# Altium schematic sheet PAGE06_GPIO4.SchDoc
size 381 x 381 mm; SheetNumber: 7; SheetTotal: 28
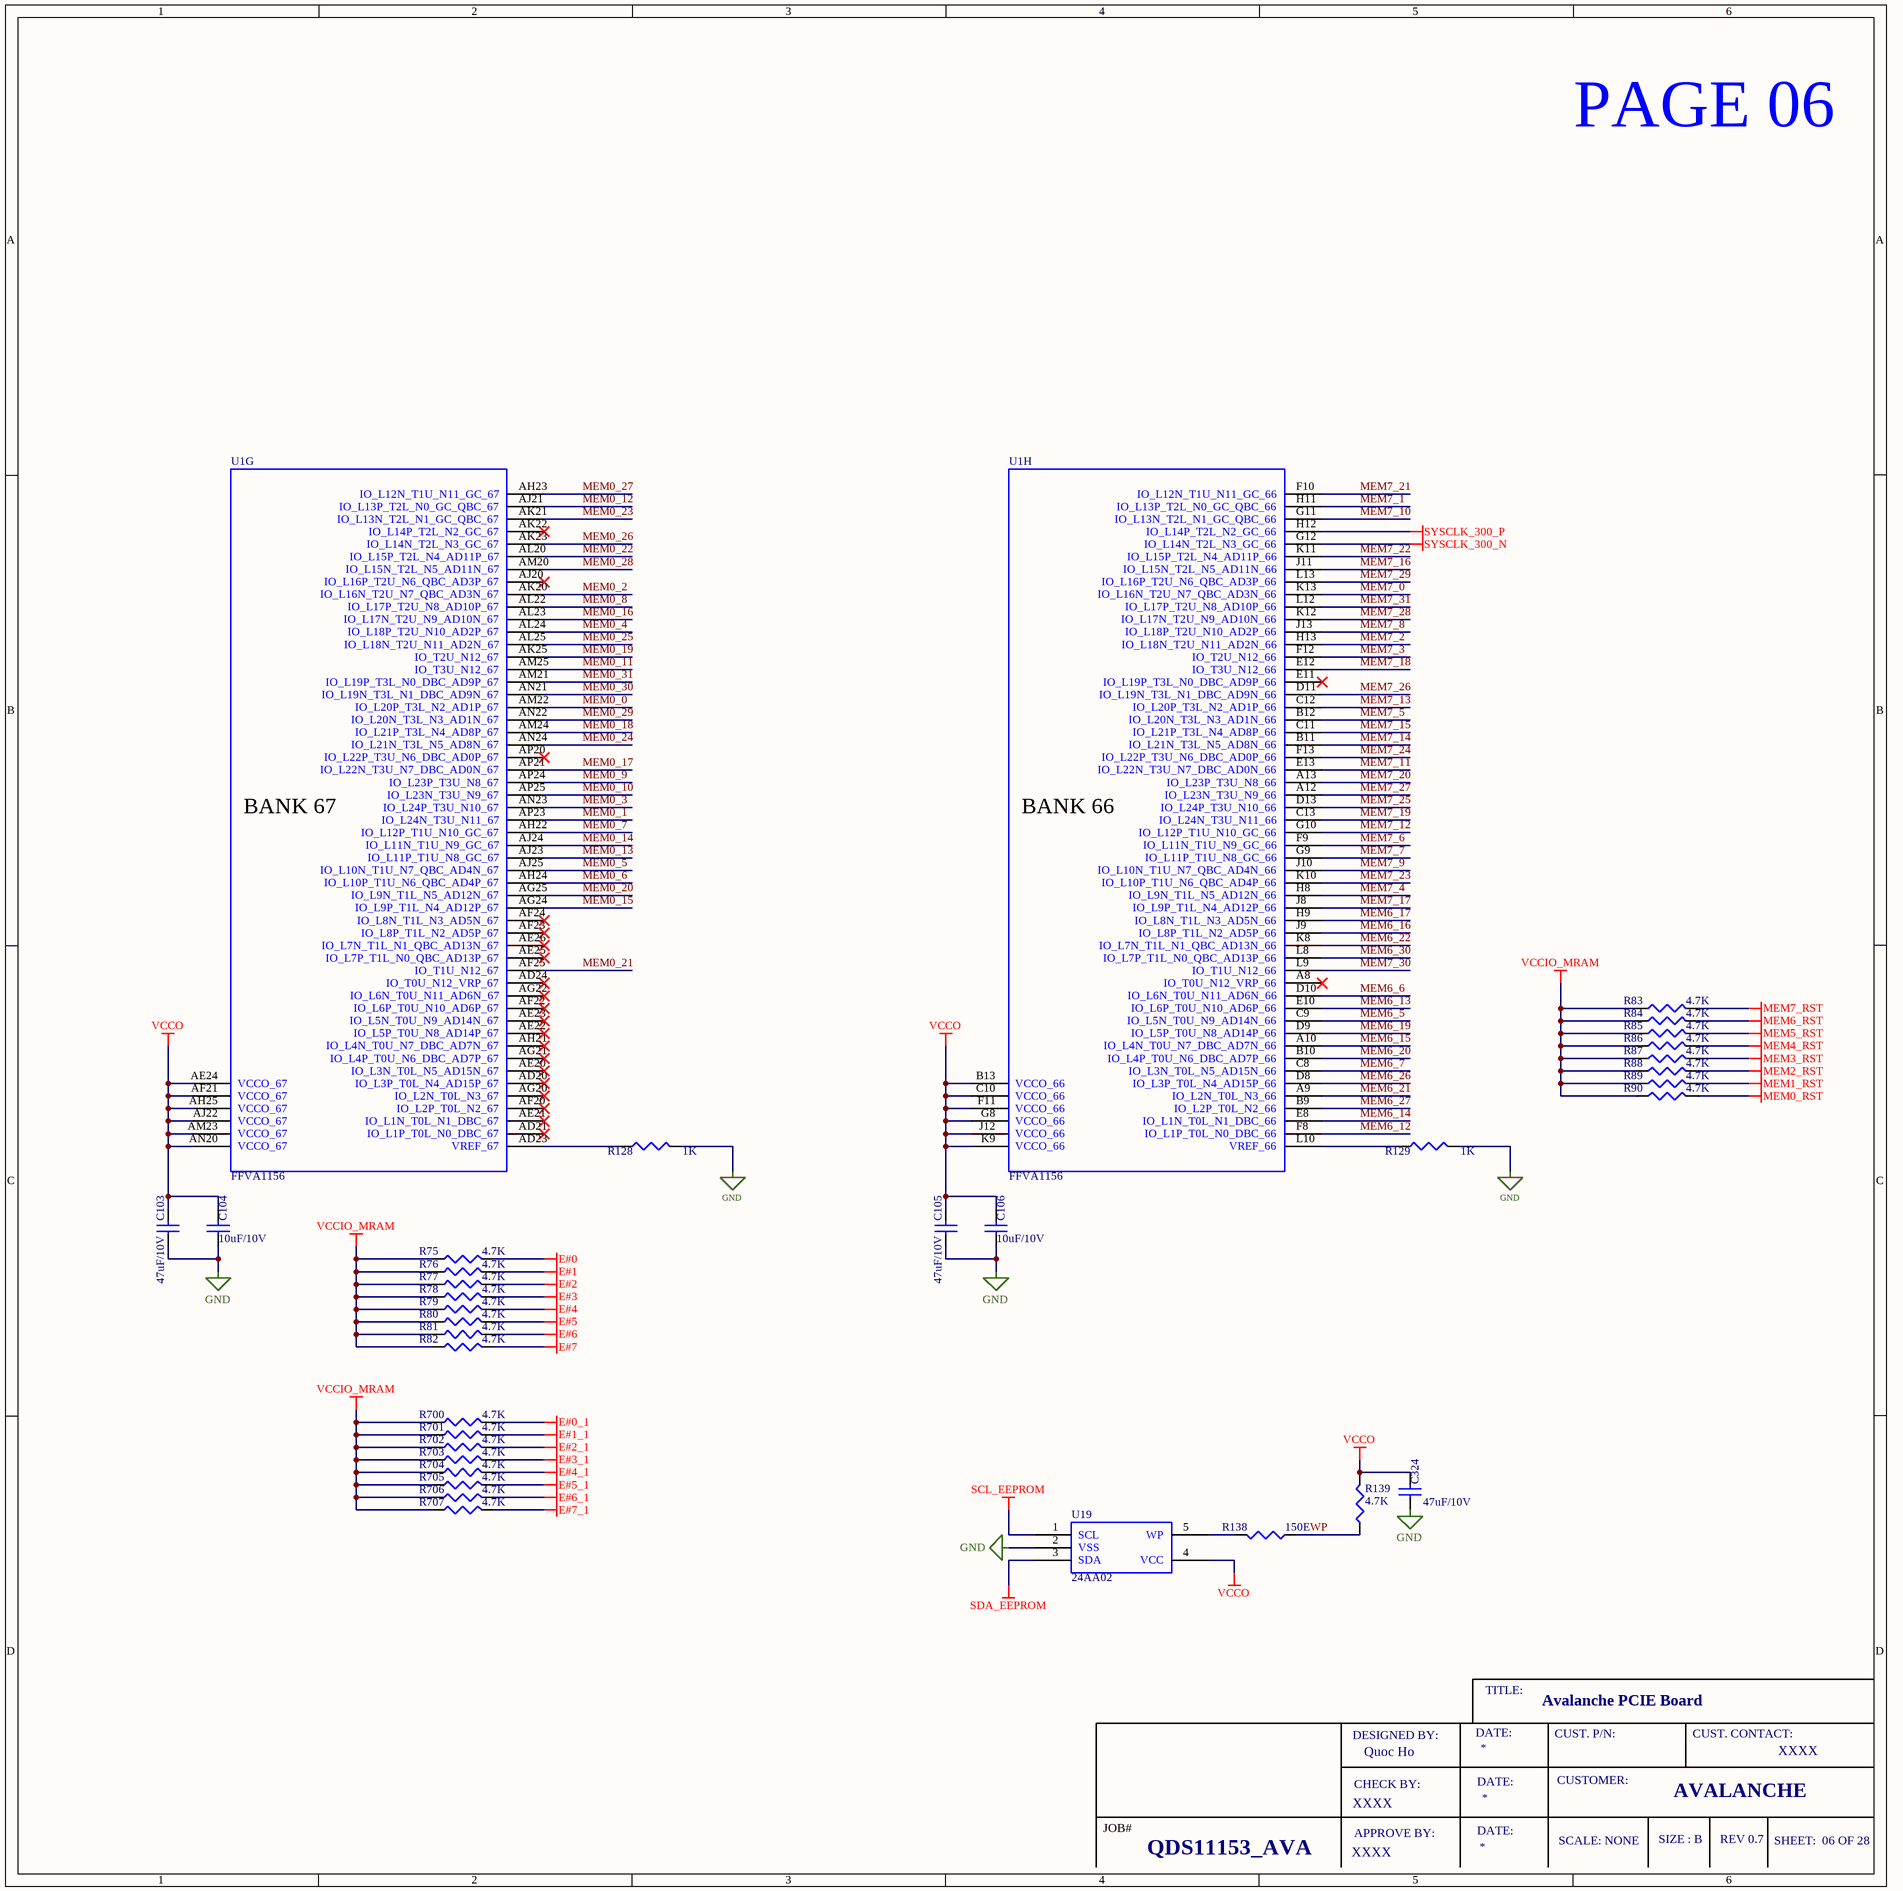
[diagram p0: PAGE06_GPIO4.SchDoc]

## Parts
C103  47uF/10V  [CN_0805]
C104  10uF/10V  [CN_0402]
C105  47uF/10V  [CN_0805]
C106  10uF/10V  [CN_0402]
C324  47uF/10V  [CN_0805]
R75  4.7K  [RN_0402]
R76  4.7K  [RN_0402]
R77  4.7K  [RN_0402]
R78  4.7K  [RN_0402]
R79  4.7K  [RN_0402]
R80  4.7K  [RN_0402]
R81  4.7K  [RN_0402]
R82  4.7K  [RN_0402]
R83  4.7K  [RN_0402]
R84  4.7K  [RN_0402]
R85  4.7K  [RN_0402]
R86  4.7K  [RN_0402]
R87  4.7K  [RN_0402]
R88  4.7K  [RN_0402]
R89  4.7K  [RN_0402]
R90  4.7K  [RN_0402]
R128  1K  [RN_0402]
R129  1K  [RN_0402]
R138  150E  [RN_0402]
R139  4.7K  [RN_0402]
R700  4.7K  [RN_0402]
R701  4.7K  [RN_0402]
R702  4.7K  [RN_0402]
R703  4.7K  [RN_0402]
R704  4.7K  [RN_0402]
R705  4.7K  [RN_0402]
R706  4.7K  [RN_0402]
R707  4.7K  [RN_0402]
U1  FFVA1156  [FFVA1156]  (parts G,H of 25)
U19  24AA02  [24AA02 - SOT23]

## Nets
E#0: R75.2
E#0_1: R700.2
E#1: R76.2
E#1_1: R701.2
E#2: R77.2
E#2_1: R702.2
E#3: R78.2
E#3_1: R703.2
E#4: R79.2
E#4_1: R704.2
E#5: R80.2
E#5_1: R705.2
E#6: R81.2
E#6_1: R706.2
E#7: R82.2
E#7_1: R707.2
GND: C103.1 C104.1 C105.1 C106.1 C324.1 R128.2 R129.2 U19.2(VSS)
MEM0_RST: R90.2
MEM1_RST: R89.2
MEM2_RST: R88.2
MEM3_RST: R87.2
MEM4_RST: R86.2
MEM5_RST: R85.2
MEM6_RST: R84.2
MEM7_RST: R83.2
SCL_EEPROM: U19.1(SCL)
SDA_EEPROM: U19.3(SDA)
SYSCLK_300_N: U1.G12(IO_L14N_T2L_N3_GC_66)
SYSCLK_300_P: U1.H12(IO_L14P_T2L_N2_GC_66)
VCCIO_MRAM: R75.1 R76.1 R77.1 R78.1 R79.1 R80.1 R81.1 R82.1 R83.1 R84.1 R85.1 R86.1 R87.1 R88.1 R89.1 R90.1 R700.1 R701.1 R702.1 R703.1 R704.1 R705.1 R706.1 R707.1
VCCO: C103.2 C104.2 C105.2 C106.2 C324.2 R139.2 U1.AE24(VCCO_67) U1.AF21(VCCO_67) U1.AH25(VCCO_67) U1.AJ22(VCCO_67) U1.AM23(VCCO_67) U1.AN20(VCCO_67) U1.B13(VCCO_66) U1.C10(VCCO_66) U1.F11(VCCO_66) U1.G8(VCCO_66) U1.J12(VCCO_66) U1.K9(VCCO_66) U19.4(VCC)
MEM0_0: U1.AM22(IO_L20P_T3L_N2_AD1P_67)
MEM0_1: U1.AP23(IO_L24N_T3U_N11_67)
MEM0_2: U1.AK20(IO_L16N_T2U_N7_QBC_AD3N_67)
MEM0_3: U1.AN23(IO_L24P_T3U_N10_67)
MEM0_4: U1.AL24(IO_L18P_T2U_N10_AD2P_67)
MEM0_5: U1.AJ25(IO_L10N_T1U_N7_QBC_AD4N_67)
MEM0_6: U1.AH24(IO_L10P_T1U_N6_QBC_AD4P_67)
MEM0_7: U1.AH22(IO_L12P_T1U_N10_GC_67)
MEM0_8: U1.AL22(IO_L17P_T2U_N8_AD10P_67)
MEM0_9: U1.AP24(IO_L23P_T3U_N8_67)
MEM0_10: U1.AP25(IO_L23N_T3U_N9_67)
MEM0_11: U1.AM25(IO_T3U_N12_67)
MEM0_12: U1.AJ21(IO_L13P_T2L_N0_GC_QBC_67)
MEM0_13: U1.AJ23(IO_L11P_T1U_N8_GC_67)
MEM0_14: U1.AJ24(IO_L11N_T1U_N9_GC_67)
MEM0_15: U1.AG24(IO_L9P_T1L_N4_AD12P_67)
MEM0_16: U1.AL23(IO_L17N_T2U_N9_AD10N_67)
MEM0_17: U1.AP21(IO_L22N_T3U_N7_DBC_AD0N_67)
MEM0_18: U1.AM24(IO_L21P_T3L_N4_AD8P_67)
MEM0_19: U1.AK25(IO_T2U_N12_67)
MEM0_20: U1.AG25(IO_L9N_T1L_N5_AD12N_67)
MEM0_21: U1.AF25(IO_T1U_N12_67)
MEM0_22: U1.AL20(IO_L15P_T2L_N4_AD11P_67)
MEM0_23: U1.AK21(IO_L13N_T2L_N1_GC_QBC_67)
MEM0_24: U1.AN24(IO_L21N_T3L_N5_AD8N_67)
MEM0_25: U1.AL25(IO_L18N_T2U_N11_AD2N_67)
MEM0_26: U1.AK23(IO_L14N_T2L_N3_GC_67)
MEM0_27: U1.AH23(IO_L12N_T1U_N11_GC_67)
MEM0_28: U1.AM20(IO_L15N_T2L_N5_AD11N_67)
MEM0_29: U1.AN22(IO_L20N_T3L_N3_AD1N_67)
MEM0_30: U1.AN21(IO_L19N_T3L_N1_DBC_AD9N_67)
MEM0_31: U1.AM21(IO_L19P_T3L_N0_DBC_AD9P_67)
MEM6_5: U1.C9(IO_L5N_T0U_N9_AD14N_66)
MEM6_6: U1.D10(IO_L6N_T0U_N11_AD6N_66)
MEM6_7: U1.C8(IO_L3N_T0L_N5_AD15N_66)
MEM6_12: U1.F8(IO_L1P_T0L_N0_DBC_66)
MEM6_13: U1.E10(IO_L6P_T0U_N10_AD6P_66)
MEM6_14: U1.E8(IO_L1N_T0L_N1_DBC_66)
MEM6_15: U1.A10(IO_L4N_T0U_N7_DBC_AD7N_66)
MEM6_16: U1.J9(IO_L8P_T1L_N2_AD5P_66)
MEM6_17: U1.H9(IO_L8N_T1L_N3_AD5N_66)
MEM6_19: U1.D9(IO_L5P_T0U_N8_AD14P_66)
MEM6_20: U1.B10(IO_L4P_T0U_N6_DBC_AD7P_66)
MEM6_21: U1.A9(IO_L2N_T0L_N3_66)
MEM6_22: U1.K8(IO_L7N_T1L_N1_QBC_AD13N_66)
MEM6_26: U1.D8(IO_L3P_T0L_N4_AD15P_66)
MEM6_27: U1.B9(IO_L2P_T0L_N2_66)
MEM6_30: U1.L8(IO_L7P_T1L_N0_QBC_AD13P_66)
MEM7_0: U1.K13(IO_L16N_T2U_N7_QBC_AD3N_66)
MEM7_1: U1.H11(IO_L13P_T2L_N0_GC_QBC_66)
MEM7_2: U1.H13(IO_L18N_T2U_N11_AD2N_66)
MEM7_3: U1.F12(IO_T2U_N12_66)
MEM7_4: U1.H8(IO_L9N_T1L_N5_AD12N_66)
MEM7_5: U1.B12(IO_L20N_T3L_N3_AD1N_66)
MEM7_6: U1.F9(IO_L11N_T1U_N9_GC_66)
MEM7_7: U1.G9(IO_L11P_T1U_N8_GC_66)
MEM7_8: U1.J13(IO_L18P_T2U_N10_AD2P_66)
MEM7_9: U1.J10(IO_L10N_T1U_N7_QBC_AD4N_66)
MEM7_10: U1.G11(IO_L13N_T2L_N1_GC_QBC_66)
MEM7_11: U1.E13(IO_L22N_T3U_N7_DBC_AD0N_66)
MEM7_12: U1.G10(IO_L12P_T1U_N10_GC_66)
MEM7_13: U1.C12(IO_L20P_T3L_N2_AD1P_66)
MEM7_14: U1.B11(IO_L21N_T3L_N5_AD8N_66)
MEM7_15: U1.C11(IO_L21P_T3L_N4_AD8P_66)
MEM7_16: U1.J11(IO_L15N_T2L_N5_AD11N_66)
MEM7_17: U1.J8(IO_L9P_T1L_N4_AD12P_66)
MEM7_18: U1.E12(IO_T3U_N12_66)
MEM7_19: U1.C13(IO_L24N_T3U_N11_66)
MEM7_20: U1.A13(IO_L23P_T3U_N8_66)
MEM7_21: U1.F10(IO_L12N_T1U_N11_GC_66)
MEM7_22: U1.K11(IO_L15P_T2L_N4_AD11P_66)
MEM7_23: U1.K10(IO_L10P_T1U_N6_QBC_AD4P_66)
MEM7_24: U1.F13(IO_L22P_T3U_N6_DBC_AD0P_66)
MEM7_25: U1.D13(IO_L24P_T3U_N10_66)
MEM7_26: U1.D11(IO_L19N_T3L_N1_DBC_AD9N_66)
MEM7_27: U1.A12(IO_L23N_T3U_N9_66)
MEM7_28: U1.K12(IO_L17N_T2U_N9_AD10N_66)
MEM7_29: U1.L13(IO_L16P_T2U_N6_QBC_AD3P_66)
MEM7_30: U1.L9(IO_T1U_N12_66)
MEM7_31: U1.L12(IO_L17P_T2U_N8_AD10P_66)
WP: R138.1 R139.1
NetR128_1: R128.1 U1.AD23(VREF_67)
NetR129_1: R129.1 U1.L10(VREF_66)
NetR138_2: R138.2 U19.5(WP)

Not connected (* = marked no-connect by the designer): U1 A8(IO_T0U_N12_VRP_66)* AD20(IO_L3P_T0L_N4_AD15P_67)* AD21(IO_L1P_T0L_N0_DBC_67)* AD24(IO_T0U_N12_VRP_67)* AE20(IO_L3N_T0L_N5_AD15N_67)* AE21(IO_L1N_T0L_N1_DBC_67)* AE22(IO_L5P_T0U_N8_AD14P_67)* AE23(IO_L5N_T0U_N9_AD14N_67)* AE25(IO_L7P_T1L_N0_QBC_AD13P_67)* AE26(IO_L7N_T1L_N1_QBC_AD13N_67)* AF20(IO_L2P_T0L_N2_67)* AF22(IO_L6P_T0U_N10_AD6P_67)* AF23(IO_L8P_T1L_N2_AD5P_67)* AF24(IO_L8N_T1L_N3_AD5N_67)* AG20(IO_L2N_T0L_N3_67)* AG21(IO_L4P_T0U_N6_DBC_AD7P_67)* AG22(IO_L6N_T0U_N11_AD6N_67)* AH21(IO_L4N_T0U_N7_DBC_AD7N_67)* AJ20(IO_L16P_T2U_N6_QBC_AD3P_67)* AK22(IO_L14P_T2L_N2_GC_67)* AP20(IO_L22P_T3U_N6_DBC_AD0P_67)* E11(IO_L19P_T3L_N0_DBC_AD9P_66)*

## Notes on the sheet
- PAGE 06
- (near U1) BANK 67
- (near U1) BANK 66
- TITLE:
- Avalanche PCIE Board
- DESIGNED BY:
- CHECK BY:
- Quoc Ho
- DATE:
- CUST. P/N:
- CUSTOMER:
- CUST. CONTACT:
- XXXX
- JOB#
- APPROVE BY:
- SCALE: NONE
- SIZE : B
- AVALANCHE
- REV 0.7
- SHEET:  06 OF 28
- QDS11153_AVA

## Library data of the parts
C103 C105 C324 = CAP: CAP CER 47UF 10V X5R 0805; Manufacturer: Murata Electronics; Manufacturer Part Number: GRM21BR61A476ME15K
C104 C106 = CAP: CAP CER 10UF 10V X5R 0402; Manufacturer Part Number: GRM155R61A106ME11D; Manufacturer: Murata Electronics
R75-R90 R139 R700-R707 = RES: RES 4.7K OHM 1% 1/16W 0402; Manufacturer Part Number: RC0402FR-134K7L; Manufacturer: YAGEO
R128 R129 = RES: RES 1K OHM 1% 1/16W 0402; Manufacturer Part Number: RC0402FR-131KL; Manufacturer: YAGEO
R138 = RES: RES 150 OHM 1% 1/16W 0402; Manufacturer Part Number: RC0402FR-07150RL; Manufacturer: YAGEO
U1 = FFVA1156: IC FPGA 516 I/O 1156FCBGA; Manufacturer: AMD; Manufacturer Part Number: XCKU15P-1FFVA1156E
U19 = 24AA02: IC EEPROM 2KBIT I2C SOT23-5; Manufacturer Part Number: 24AA02UIDT-I/OT; Manufacturer: Microchip Technology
